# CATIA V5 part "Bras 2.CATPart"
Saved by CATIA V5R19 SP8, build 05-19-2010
Part number: Bras 2
Bounding box of the stored display mesh (mm): x 75 to 225, y -112.5 to 1312.5, z -1912.31 to -637.69
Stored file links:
  C:\Users\ThinkMotion\Desktop\EU_thinkMotion\iao\IAO_MMS_Groupe3\fovide\fovide\Bras 2.CATPart
  C:\Users\ThinkMotion\Desktop\EU_thinkMotion\iao\IAO_MMS_Groupe3\fovide\fovide\fovide.CATProduct
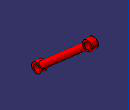
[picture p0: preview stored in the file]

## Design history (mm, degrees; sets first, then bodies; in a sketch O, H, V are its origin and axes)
External parameters (linked from other documents)
  `External.Diamètre bielle` = 150 mm
  `External.Rayon bielle` = 75 mm
Set1
  Plane1: linked copy from another document
  Line1: linked copy from another document
  Point1 "Point.B": linked copy from another document
  Point2 "Point.C": linked copy from another document
  Line2: linked copy from another document
  Line3: linked copy from another document
Body1 (main body)
  Sketch1 on Plane1, origin (150, 0, 0), H (0, 1, 0), V (0, 0, 1)
    point P1 (1200, -750)
    line L1 (1200, -750) -> (1249.3878, -806.4433)
    line L2 (1249.3878, -806.4433) -> (49.3878, -1856.4433)
    line L3 (49.3878, -1856.4433) -> (0, -1800)
    line L4 (0, -1800) -> (1200, -750)
    point P4 (0, -1800)
    reference projected line E1 (1200, -750) -> (0, -1800) from Line1
    reference projected point E2 (1200, -750) from Point1
    reference projected point E3 (0, -1800) from Point2
    length L1 = 75 {= `External.Diamètre bielle` /2}
    parallelism: L4 E1, L4 L2, L1 L3
    coincidence: P1 E2, P4 E3
    perpendicularity: L1 L4
  Shaft1: profile Sketch1, axis Sketch1.L4, angle 360
  Sketch2 on Plane1, origin (150, 0, 0), H (0, 1, 0), V (0, 0, 1)
    circle A1 centre (1200, -750) radius 112.5
    point P1 (1200, -750)
    reference projected point E1 (1200, -750) from Point1
    radius A1 = 112.5 {= `External.Diamètre bielle` /2*1.5}
    coincidence: P1 E1
  Pad1: profile Sketch2, direction (1, 0, 0), length 75 {= `External.Diamètre bielle` /2}, mirrored extent
  Sketch3 on Plane1, origin (150, 0, 0), H (0, 1, 0), V (0, 0, 1)
    circle A1 centre (0, -1800) radius 112.5
    point P1 (0, -1800)
    reference projected point E1 (0, -1800) from Point2
    radius A1 = 112.5 {= `External.Diamètre bielle` /2*1.5}
    coincidence: P1 E1
  Pad2: profile Sketch3, direction (1, 0, 0), length 75 {= `External.Diamètre bielle` /2}, mirrored extent
  Sketch4 on end face of Pad2, origin (225, 0, -1800), H (0, 1, 0), V (0, 0, 1)
    point P1 (0, 0)
    intersected point E1 (0, 0) from Line2
    coincidence: E1 P1
  Hole1: placed by Sketch4, at (225, 0, -1800) direction (-1, 0, 0), diameter 150 {= `External.Diamètre bielle`}, through (limit type 6)
  Sketch5 on end face of Pad1, origin (225, 1200, -750), H (0, 1, 0), V (0, 0, 1)
    point P1 (0, 0)
    intersected point E1 (0, 0) from Line3
    coincidence: E1 P1
  Hole2: placed by Sketch5, at (225, 1200, -750) direction (-1, 0, 0), diameter 150 {= `External.Diamètre bielle`}, through (limit type 6)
